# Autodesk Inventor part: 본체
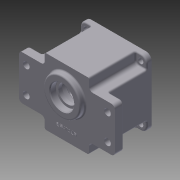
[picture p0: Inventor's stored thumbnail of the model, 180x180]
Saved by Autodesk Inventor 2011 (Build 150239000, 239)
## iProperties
Created: 2014-12
Part Number: 본체
Material: 알루미늄-6061
Document SubType Name: Modeling
Designer: Administrator
Mass: 705.383 g
Surface Area: 672.962 cm^2
Volume: 260.289 cm^3
Density: 2.71 g/cm^3
Author: Administrator
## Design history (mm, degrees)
sketch "스케치1"
  geometry: L1 (45, 45)-(-45, 45); L2 (-45, 45)-(-45, -45); L3 (-45, -45)-(45, -45); L4 (45, -45)-(45, 45); 3 further points
  constraints: 8 end point, 2 midpoint, 2 parallel, 1 horizontal, 1 horizontal alignment, 1 perpendicular, 1 vertical alignment
  dimensions: "d0" = 90 distance of L1.start L1.end; "d1" = 90 distance of L3.end L1.start
extrude "돌출1" new body sketch "스케치1" distance "d2" = 70; taper "d3" = 0 deg
sketch "스케치2"
  geometry: L1 (-65, 30)-(65, 30); L2 (65, 30)-(65, -30); L3 (65, -30)-(-65, -30); L4 (-65, -30)-(-65, 30); 3 further points
  constraints: 8 end point, 2 midpoint, 2 parallel, 1 horizontal, 1 horizontal alignment, 1 perpendicular, 1 vertical alignment
  dimensions: "d4" = 60 distance of L3.end L1.start; "d5" = 130 distance of L1.start L1.end
extrude "돌출2" join sketch "스케치2" distance "d6" = 12; taper "d7" = 0 deg
sketch "스케치3"
  geometry: C1 r 40 at (0, 0); 1 further point
  constraints: 1 centre point, 1 coincident
  dimensions: "d8" = 80 diameter of C1
extrude "돌출3" cut sketch "스케치3" distance "d9" = 9; taper "d10" = 0 deg
hole "Hole1" diameter "d13" = 78; stored, may be unused: countersink angle "d17" = 90 deg, drill point angle "d19" = 0 deg; dims "d11" = 10, "d12" = 10, "d14" = 6, "d15" = 4, "d16" = 2, "d18" = 52
sketch "스케치4"
  geometry: C1 r 25 at (0, 11); 1 further point
  constraints: 1 centre point, 1 vertical alignment
  dimensions: "d20" = 50 diameter of C1; "d21" = 11 distance of C1.centre point (0, 0)
extrude "돌출4" join sketch "스케치4" distance "d22" = 7; taper "d23" = 0 deg
sketch "스케치5"
  geometry: C1 r 39 at (0, 0) reference; C2 r 20.5 at (0, -11); C3 r 14 at (0, 20)
  constraints: 2 centre point, 2 vertical alignment
  dimensions: "d24" = 41 diameter of C2; "d25" = 28 diameter of C3; "d26" = 11 distance of C2.centre C1.centre; "d27" = 20 distance of C1.centre C3.centre
extrude "돌출5" join sketch "스케치5" distance "d28" = 7; taper "d29" = 0 deg
sketch "스케치6"
  geometry: L1 (0, 0)-(24.749, 24.749); L2 (0, 0)-(35, 0); C1 r 39 at (0, 0) reference; A1 r 35 centre (0, 0) between (24.749, 24.749) and (21.762, 27.412); A2 r 4 centre (24.749, 24.749) between (21.809, 27.462) and (27.462, 21.809); A3 r 39 centre (0, 0) between (32.777, 21.134) and (21.134, 32.777); A4 r 3.5 centre (29.836, 19.238) between (32.777, 21.134) and (27.412, 21.762); A5 r 3.5 centre (19.238, 29.836) between (21.762, 27.412) and (21.134, 32.777)
  constraints: 13 point on circle, 5 centre point, 4 end point, 4 tangent, 3 coincident, 1 equal length, 1 horizontal
  dimensions: "d75" = 70 diameter of A1; "d76" = 45 deg angle of L2 L1; "d77" = 8 diameter of A2; "d78" = 7 diameter of A4; "d79" = 7 diameter of A5
extrude "돌출6" join sketch "스케치6" stored distance "d80" = 7; taper "d81" = 0 deg
sketch "스케치7"
  geometry: L1 (45, 45)-(45, 30) reference; L2 (-45, 45)-(45, 45) reference; L3 (45, 30)-(30, 30); L4 (30, 30)-(30, 45); L5 (30, 45)-(45, 45); L6 (45, 45)-(45, 30); 1 further point
  constraints: 8 end point, 2 parallel, 1 horizontal, 1 perpendicular, 1 point on line
  dimensions: "d85" = 30 distance from line of L4 point (0, 0)
extrude "돌출7" cut sketch "스케치7" distance "d86" = 63; taper "d87" = 0 deg
fillet "모깎기1" dims "d91" = 5, "d92" = 8
hole "Hole7" diameter "d95" = 7; stored, may be unused: countersink angle "d99" = 90 deg, drill point angle "d101" = 0 deg; dims "d93" = 10, "d94" = 10, "d96" = 6, "d97" = 4, "d98" = 2, "d100" = 7
hole "Hole8" diameter "d107" = 3.459; stored, may be unused: countersink angle "d111" = 90 deg, drill point angle "d113" = 118 deg; dims "d105" = 10, "d106" = 10, "d108" = 12, "d109" = 4, "d110" = 2, "d112" = 15
sketch "스케치8"
  geometry: 2 further points
  dimensions: "d117" = 55 horizontal distance of point (0, 0) point (-55, 17.5); "d118" = 17.5 vertical distance of point (-55, 17.5) point (0, 0)
hole "Hole9" sketch "스케치8" at (-55, 17.5) diameter "d119" = 9; stored, may be unused: countersink angle "d123" = 90 deg, drill point angle "d125" = 0 deg; dims "d120" = 12, "d121" = 4, "d122" = 2, "d124" = 12
sketch "스케치11"
  geometry: C1 r 17.5 at (0, -11); A1 r 20.5 centre (0, -11) between (-7.402, 8.117) and (7.402, 8.117) reference; 1 further point
  constraints: 1 centre point, 1 coincident
  dimensions: "d144" = 35 diameter of C1
extrude "돌출9" cut sketch "스케치11" distance "d145" = 10; taper "d146" = 0 deg
sketch "스케치12"
  geometry: C1 r 17.5 at (0, 0) reference; C2 r 12.5 at (0, 0); 1 further point
  constraints: 1 centre point, 1 coincident
  dimensions: "d147" = 25 diameter of C2
extrude "돌출10" cut sketch "스케치12" distance "d148" = 5; taper "d149" = 0 deg
sketch "스케치13"
  geometry: C1 r 25 at (0, 0) reference; C2 r 16 at (0, 0); 1 further point
  constraints: 1 centre point, 1 coincident
  dimensions: "d150" = 32 diameter of C2
extrude "돌출11" cut sketch "스케치13" distance "d151" = 8; taper "d152" = 0 deg
sketch "스케치14"
  geometry: C1 r 11 at (0, 20); A1 r 14 centre (0, 20) between (7.402, 8.117) and (-7.402, 8.117) reference; 1 further point
  constraints: 1 centre point, 1 coincident
  dimensions: "d153" = 22 diameter of C1
extrude "돌출12" cut sketch "스케치14" distance "d154" = 7; taper "d155" = 0 deg
sketch "스케치15"
  geometry: C1 r 11 at (0, 0) reference; C2 r 9.5 at (0, 0); 1 further point
  constraints: 1 centre point, 1 coincident
  dimensions: "d156" = 19 diameter of C2
extrude "돌출13" cut sketch "스케치15" distance "d157" = 1; taper "d158" = 0 deg
sketch "스케치17"
  geometry: A1 r 20.5 centre (0, -11) between (-7.402, 8.117) and (7.402, 8.117) reference; A2 r 14 centre (0, 20) between (7.402, 8.117) and (-7.402, 8.117) reference; A3 r 3 centre (12.742, 8.746) between (10.493, 10.732) and (11.115, 6.225); A4 r 3 centre (-12.742, 8.746) between (-11.115, 6.225) and (-10.493, 10.732); A5 r 14 centre (0, 20) between (-10.493, 10.732) and (-7.402, 8.117); A6 r 20.5 centre (0, -11) between (-7.402, 8.117) and (-11.115, 6.225); A7 r 14 centre (0, 20) between (7.402, 8.117) and (10.493, 10.732); A8 r 20.5 centre (0, -11) between (11.115, 6.225) and (7.402, 8.117)
  constraints: 16 point on circle, 6 centre point, 4 concentric, 4 tangent
  dimensions: "d167" = 6 diameter of A3; "d168" = 6 diameter of A4
extrude "돌출15" join sketch "스케치17" stored distance "d169" = 1; taper "d170" = 0 deg
chamfer "모따기2" distance "d159" = 1; stored, may be unused: second distance "d160" = 2, angle "d161" = 45 deg
fillet "모깎기4" dims "d171" = 2, "d172" = 0.3
sketch "스케치18"
  geometry: L1 (28, -45)-(-28, -45) reference; 2 further points
  constraints: 1 vertical alignment, 1 other
  dimensions: "d173" = 15 distance from line of point (0, -30) L1
feature "엠보싱2" sketch "스케치18" dims "d0" = 90, "d1" = 90, "d174" = 0.5, "d175" = 0
fillet "모깎기5" dims "d176" = 5
node "솔리드1"
pattern_circular "원형 패턴1" dims angle "d83" = 360 deg
pattern_circular "원형 패턴2" dims angle "d89" = 360 deg
pattern_circular "원형 패턴3" dims angle "d103" = 360 deg
pattern_circular "원형 패턴4" dims angle "d115" = 360 deg
pattern_linear "직사각형 패턴1" dims "d128" = 110, "d131" = 35
